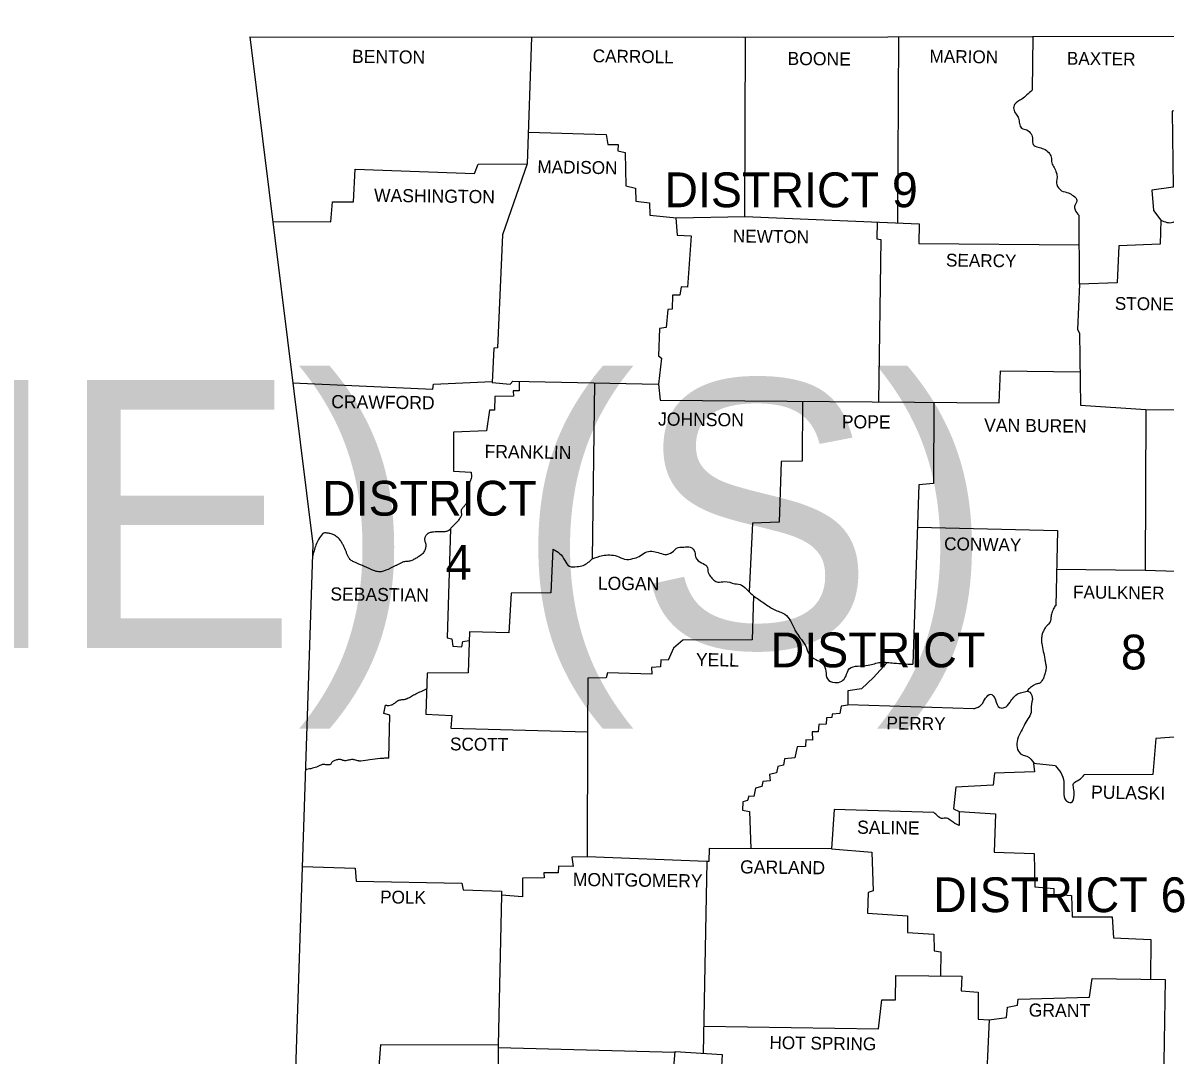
# Model space of a CAD drawing. Extents: x 164 to 3385, y 68 to 2119.
# Drawn here: x 2632.5 to 2994.5, y 1627.9 to 1955.2 of the extents above; entities that cross this region are included whole.
import ezdxf

# ---------------------------------------------------------------- set-up
doc = ezdxf.new("R2010")
doc.units = 0
doc.layers.add('2', color=7, linetype='Continuous')
doc.layers.add('Default', color=7, linetype='Continuous')

msp = doc.modelspace()

# ---------------------------------------------------------------- linework, layer by layer
at = {"layer": 'Default'}
msp.add_line((2849.29, 1689.32), (2848.17, 1628.55), dxfattribs=at)
for points in [[(2704.43, 1950.7), (2860.9, 1950.6), (2998.22, 1950.89), (3160.21, 1953.41), (3235.3, 1955.15)], [(2704.43, 1950.7), (2724.46, 1789.87), (2715.75, 1527.33)], [(2793.76, 1950.65), (2792.39, 1910.44)], [(2792.74, 1920.53), (2817.36, 1919.73), (2817.94, 1916.64), (2821.23, 1916.54), (2821.13, 1914.6), (2823.45, 1914.02), (2823.65, 1903.48), (2826.65, 1902.8), (2826.84, 1898.64), (2831.1, 1898.06), (2831.29, 1894.19), (2839.71, 1893.32), (2861.39, 1893.8), (2861.58, 1950.61)], [(2910.07, 1950.71), (2909.77, 1891.76)], [(2952.65, 1950.8), (2952.45, 1933.77)], [(2998.21, 1950.89), (2998.41, 1927.28), (2996.77, 1927.19), (2997.06, 1903.09), (2990.28, 1902.12), (2990.86, 1895.64), (2993.19, 1892.64), (2992.99, 1884.99), (2979.83, 1884.51), (2979.35, 1872.7), (2967.35, 1872.32), (2966.77, 1857.99), (2967.45, 1856.83), (2967.74, 1833.99), (2988.45, 1832.64), (2988.16, 1781.64), (3004.61, 1781.16), (3004.61, 1729.29), (2991.64, 1728.32), (2990.67, 1716.9), (2968.9, 1716.81)], [(2711.72, 1892.16), (2730.17, 1892.06), (2730.65, 1898.44), (2737.33, 1898.44), (2737.91, 1908.8), (2775.65, 1907.44), (2776.81, 1910.35), (2792.39, 1910.44), (2784.55, 1887.99), (2783, 1852.09), (2781.84, 1851.99), (2781.26, 1841.16), (2786.97, 1840.67), (2787.84, 1841.54), (2834, 1840.67), (2834.49, 1835.54)], [(2839.5, 1893.34), (2839.9, 1887.9), (2844.36, 1887.61), (2843.19, 1871.35), (2841.16, 1871.45), (2840.78, 1868.83), (2838.45, 1868.83), (2838.36, 1864.38), (2836.9, 1864.28), (2836.42, 1858.57), (2834.29, 1858.28), (2834, 1849.57), (2834.97, 1848.9), (2834, 1840.67)], [(2861.39, 1893.8), (2916.55, 1891.48), (2916.45, 1885.19), (2967.29, 1884.8)], [(2967.35, 1872.32), (2967.25, 1894.09)], [(2903.29, 1892.03), (2903.19, 1886.73), (2904.45, 1886.44), (2903.67, 1834.98)], [(2834.49, 1835.54), (2941.9, 1834.67), (2942.38, 1844.83), (2967.6, 1844.54)], [(2718.08, 1841.08), (2762.49, 1839.03), (2762.68, 1840.58), (2781.28, 1841.46)], [(2789.78, 1841.51), (2789.78, 1838.54), (2787.94, 1838.54), (2788.04, 1836.8), (2782.13, 1836.7), (2782.04, 1832.35), (2780.39, 1832.35), (2779.52, 1825.87), (2769.07, 1825.38), (2768.97, 1813.09), (2774.58, 1812.71)], [(2813.68, 1841.06), (2813, 1785.22)], [(2879.61, 1835.18), (2879.51, 1816.22), (2872.83, 1816.12), (2872.25, 1796.87), (2863.74, 1796.58), (2862.68, 1774.86)], [(2921.29, 1834.84), (2921.09, 1809.12), (2916.45, 1808.74), (2914.61, 1751.84)], [(2988.45, 1832.64), (3038.19, 1832.35), (3042.44, 1834.38), (3042.15, 1796.54), (3039.25, 1795.29), (3036.64, 1793.06), (3035.77, 1792.19), (3035.67, 1781.35), (2998.02, 1781.35)], [(2768.04, 1794.78), (2767.04, 1760.26), (2768.49, 1759.87), (2768.78, 1757.55), (2771.68, 1757.35), (2771.97, 1759), (2774.02, 1759.34)], [(2916.01, 1795.29), (2960.48, 1794.22), (2959.9, 1770.32)], [(2800.52, 1788.32), (2799.84, 1774.48), (2787.26, 1774.38), (2786.58, 1761.8), (2774.1, 1762.09), (2773.71, 1749.13), (2760.65, 1749.03), (2760.26, 1736.06), (2768.49, 1735.58), (2768.2, 1731.61), (2811.49, 1730.41)], [(2960, 1782.03), (2988.16, 1781.64)], [(2864.1, 1773.51), (2863.71, 1759.58), (2841.65, 1759.48), (2838.74, 1756.97), (2837.1, 1753.09), (2834.68, 1753.29), (2834.58, 1751.06), (2831.78, 1750.77), (2831.87, 1748.74), (2817.84, 1749.13), (2817.36, 1747.58), (2811.55, 1747.38), (2811.49, 1730.41)], [(2906.44, 1752.35), (2902.13, 1747.68), (2898.35, 1744.09), (2894, 1743.42), (2894, 1738.87), (2891.87, 1738.58), (2891.48, 1736.26), (2889.06, 1736.06), (2888.87, 1735), (2887.22, 1734.9), (2887.13, 1732.87), (2884.81, 1732.77), (2884.61, 1730.45), (2882.68, 1730.45), (2882.77, 1727.74), (2880.64, 1727.93), (2880.55, 1725.8), (2877.93, 1725.61), (2877.16, 1722.13), (2873.87, 1721.84), (2873.58, 1719.9), (2871.84, 1719.42), (2871.35, 1717.39), (2869.13, 1716.9), (2869.32, 1714.87), (2867.1, 1714.68), (2866.71, 1713.13), (2864.68, 1712.55), (2864.19, 1709.93), (2862.65, 1710.03), (2862.16, 1708.68), (2860.71, 1708.19), (2860.61, 1705.58), (2862.84, 1705.19), (2863.24, 1693.42)], [(2748.55, 1722.03), (2748.84, 1735.68), (2746.91, 1736.26), (2747.49, 1738.87)], [(2933.96, 1737.71), (2894, 1738.97)], [(2811.49, 1730.41), (2811.36, 1690.77), (2806.52, 1690.68), (2806.91, 1687.77), (2802.26, 1687.87), (2802.16, 1685.74), (2797.62, 1685.74), (2797.71, 1684.19), (2790.94, 1684), (2790.84, 1678.1), (2784.26, 1678.68), (2783.2, 1631.07), (2745.94, 1631.16), (2745.07, 1620.13), (2746.42, 1619.16), (2746.33, 1606.78), (2718.43, 1608)], [(2959.8, 1719.61), (2952.83, 1720.39), (2953.12, 1717.77), (2940.45, 1717.29), (2940.06, 1713.52), (2928.16, 1712.84), (2927.48, 1706.06), (2929.22, 1705.19), (2929.22, 1700.74)], [(2921.29, 1704.81), (2889.64, 1705.77), (2888.77, 1693.29), (2850.07, 1693.48), (2849.91, 1689.3)], [(2929.22, 1705.14), (2940.74, 1704.42), (2940.35, 1692.32), (2953.03, 1691.84), (2953.22, 1681.29), (2959.22, 1680.81), (2959.22, 1678.97), (2964.83, 1678.58), (2965.03, 1671.81), (2977.8, 1671.81), (2978.19, 1665.13), (2989.99, 1664.55), (2989.9, 1651.95)], [(2849.29, 1689.32), (2811.36, 1690.77)], [(2888.77, 1693.29), (2901.64, 1692.23), (2902.03, 1680.03), (2900.39, 1679.45), (2900.19, 1672.97), (2912.87, 1672.1), (2912.87, 1666.77), (2921.29, 1666.29), (2921.38, 1660.97), (2923.42, 1660.68), (2923.31, 1653.03)], [(2721.07, 1687.77), (2737.81, 1687.19), (2738.2, 1683.13), (2771.68, 1682.45), (2772.07, 1680.32), (2784.26, 1679.94), (2784.26, 1678.68)], [(2849.91, 1689.3), (2849.29, 1689.32)], [(2848.32, 1637.07), (2903.68, 1636.29), (2904.74, 1645.49), (2909.09, 1645.49), (2909.19, 1653.23), (2930.09, 1652.94), (2929.9, 1648.29), (2935.32, 1647.9), (2935.32, 1639.39), (2938.8, 1639.1), (2938.76, 1638.21)], [(2938.8, 1639.1), (2944.22, 1639.87), (2944.61, 1643.16), (2947.8, 1643.74), (2948, 1645.68), (2970.54, 1646.36), (2971.41, 1652.26), (2994.54, 1651.87)], [(2994.54, 1651.87), (2993.96, 1612.58), (2991.74, 1612.49), (2991.45, 1588.2)], [(2938.8, 1639.1), (2937.64, 1613.74), (2936.77, 1614.03), (2936.87, 1600.98)], [(2783.2, 1631.07), (2783.2, 1618.2), (2785.33, 1617.81), (2785.13, 1605.81), (2797.91, 1604.84), (2796.36, 1540.88), (2770.04, 1541.55)], [(2783.2, 1630.39), (2839.21, 1628.92)], [(2836.9, 1611.23), (2836.71, 1616.55), (2838.26, 1616.65), (2839.23, 1629.13), (2854.13, 1628.16), (2853.74, 1620.52), (2873, 1619.45), (2873.1, 1614.81), (2890.51, 1613.74), (2893.51, 1608.52), (2891.68, 1606.2), (2892.55, 1602.62), (2955.64, 1600.29)]]:
    msp.add_lwpolyline(points, dxfattribs=at)
for points in [[(2952.45, 1933.77), (2950.71, 1932.31), (2949.16, 1930.96), (2946.83, 1929.31), (2946.54, 1927.77), (2947.32, 1926.22), (2948.09, 1924.96), (2948.38, 1923.22), (2949.06, 1921.77), (2950.71, 1921.19), (2952.06, 1919.93), (2952.54, 1918.19), (2952.74, 1916.54), (2954.29, 1915.77), (2956.03, 1915.19), (2957.67, 1914.02), (2958.45, 1912.57), (2958.64, 1910.73), (2959.32, 1909.28), (2960.09, 1907.54), (2960.29, 1906.09), (2960.09, 1904.64), (2960.48, 1903.28), (2961.74, 1901.93), (2963.96, 1901.25), (2965.51, 1900.28), (2966.58, 1898.93), (2965.9, 1897.28), (2965.99, 1895.83), (2967.25, 1894.09)], [(2993.19, 1892.64), (2997.06, 1891.96), (2999.38, 1892.83), (3001.03, 1890.32), (3001.9, 1888.38), (3003.35, 1885.57), (3005.67, 1884.7), (3007.41, 1883.15), (3007.41, 1881.51), (3005.86, 1879.96), (3004.7, 1878.41), (3005.09, 1876.57), (3005.48, 1874.06), (3005.48, 1871.64), (3004.9, 1869.41), (3004.41, 1867.38), (3004.9, 1865.64), (3006.73, 1865.93), (3008.67, 1867.38), (3010.7, 1867.38), (3012.64, 1866.32), (3014.67, 1864.48), (3016.7, 1864.86), (3018.35, 1865.35), (3020.67, 1866.03), (3022.31, 1865.15), (3023.77, 1863.99), (3025.51, 1862.16), (3027.15, 1860.99), (3029.28, 1859.93), (3031.9, 1859.25), (3034.31, 1857.61), (3034.7, 1854.8), (3034.6, 1852.38), (3034.41, 1849.38), (3034.22, 1846.09), (3034.51, 1842.9), (3035.57, 1840.77), (3036.93, 1838.25), (3037.31, 1835.93), (3037.22, 1832.25)], [(2774.58, 1812.71), (2774.67, 1812.2), (2774.71, 1811.68), (2774.58, 1810.67), (2774.41, 1810.14), (2774.21, 1809.61), (2774, 1809.08), (2773.81, 1808.54), (2773.33, 1806.71), (2773.33, 1806.11), (2773.48, 1805.5), (2773.62, 1804.89), (2773.65, 1804.59), (2773.62, 1804.29), (2773.26, 1803.29), (2772.75, 1802.35), (2772.45, 1801.94), (2772.1, 1801.58), (2771.77, 1801.21), (2771.49, 1800.8), (2771.41, 1800.34), (2771.49, 1799.84), (2771.58, 1799.33), (2771.49, 1798.87), (2771.33, 1798.6), (2771.17, 1798.33), (2770.83, 1797.8), (2770.45, 1797.3), (2770.04, 1796.83), (2768.49, 1795.29), (2767.87, 1794.59), (2767.54, 1794.27), (2767.35, 1794.14), (2767.24, 1794.08), (2767.13, 1794.03), (2766.54, 1793.87), (2765.93, 1793.83), (2765.32, 1793.84), (2765.02, 1793.84), (2764.71, 1793.83), (2763.7, 1793.79), (2762.68, 1793.74), (2762.16, 1793.69), (2761.64, 1793.58), (2761.14, 1793.38), (2760.9, 1793.24), (2760.65, 1793.06), (2760.33, 1792.74), (2760.11, 1792.39), (2759.96, 1792.01), (2759.88, 1791.61), (2759.9, 1791.05), (2760.06, 1790.5), (2760.23, 1789.94), (2760.26, 1789.38), (2760.17, 1788.83), (2760.03, 1788.29), (2759.49, 1787.25), (2758.53, 1786.31), (2757.46, 1785.61), (2756.37, 1785.01), (2755.23, 1784.54), (2754.65, 1784.42), (2754.06, 1784.38), (2753.47, 1784.32), (2752.91, 1784.16), (2752.1, 1783.79), (2751.31, 1783.39), (2750.52, 1783), (2749.72, 1782.61), (2746.81, 1781.35), (2746.06, 1781.17), (2745.26, 1781.16), (2744.47, 1781.29), (2743.72, 1781.54), (2740.81, 1782.8), (2738.2, 1783.96), (2737.66, 1784.19), (2737.12, 1784.43), (2736.61, 1784.73), (2736.38, 1784.91), (2736.27, 1785.01), (2736.17, 1785.13), (2735.62, 1785.96), (2735.24, 1786.87), (2734.91, 1787.8), (2734.73, 1788.26), (2734.52, 1788.71), (2734.01, 1789.68), (2733.46, 1790.64), (2733.09, 1791.19), (2732.66, 1791.69), (2732.18, 1792.15), (2731.91, 1792.37), (2731.62, 1792.58), (2731.08, 1792.88), (2730.53, 1793.09), (2729.96, 1793.24), (2729.39, 1793.35), (2728.93, 1793.44), (2728.44, 1793.49), (2727.97, 1793.43), (2727.75, 1793.32), (2727.65, 1793.25), (2727.55, 1793.16), (2726.25, 1791.43), (2725.41, 1789.63), (2724.83, 1787.78), (2724.33, 1785.9)], [(2800.52, 1788.32), (2802.65, 1786.96), (2804.29, 1784.74), (2805.74, 1782.9), (2808.16, 1782.8), (2810.1, 1783.19), (2813, 1785.22)], [(2813, 1785.22), (2816.2, 1786.29), (2818.52, 1786.48), (2820.84, 1786.09), (2823.26, 1785.13), (2825.87, 1785.32), (2827.81, 1786), (2829.74, 1787.25), (2831.87, 1787.64), (2833.9, 1787.25), (2836.03, 1786.67), (2838.36, 1787.35), (2839.71, 1788.61), (2842.03, 1789), (2844.07, 1789), (2845.52, 1787.35), (2845.81, 1785.61), (2847.65, 1783.96), (2849.29, 1782.9), (2849.77, 1780.87), (2850.65, 1779.42), (2851.52, 1778.45), (2852.77, 1777.87), (2854.9, 1778.06), (2858.19, 1777.38), (2860.32, 1776.9), (2862.26, 1775.25), (2864.1, 1773.51)], [(2864.1, 1773.51), (2867.48, 1771.19), (2870.68, 1769.16), (2873.97, 1767.71), (2875.81, 1765.58), (2877.45, 1762.29), (2878.81, 1760.26), (2880.55, 1757.74), (2881.81, 1754.93), (2883.84, 1753.38), (2885.97, 1752.03), (2887.03, 1749.61), (2887.51, 1747.19), (2889.84, 1746.03), (2892.06, 1746.51), (2893.32, 1747.97), (2894.48, 1750.48), (2897.1, 1751.26), (2900.48, 1751.55), (2904.35, 1752.42), (2908.61, 1752.22), (2914.61, 1751.84)], [(2959.9, 1770.32), (2959.76, 1770.36), (2959.61, 1770.23), (2959.28, 1769.65), (2958.94, 1768.84), (2958.78, 1768.44), (2958.64, 1768.09), (2958.44, 1767.36), (2958.36, 1766.61), (2958.28, 1765.88), (2958.19, 1765.53), (2958.06, 1765.19), (2957.73, 1764.7), (2957.31, 1764.27), (2956.88, 1763.83), (2956.51, 1763.35), (2956.21, 1762.84), (2955.94, 1762.32), (2955.54, 1761.22), (2955.47, 1760.87), (2955.42, 1760.52), (2955.35, 1759.82), (2955.36, 1759.11), (2955.45, 1758.42), (2955.93, 1755.9), (2956.41, 1753.48), (2956.62, 1752.37), (2956.72, 1751.81), (2956.8, 1751.26), (2956.82, 1750.55), (2956.71, 1749.85), (2956.53, 1749.15), (2956.42, 1748.8), (2956.32, 1748.45), (2956.11, 1747.79), (2955.85, 1747.16), (2955.51, 1746.57), (2955.3, 1746.3), (2955.18, 1746.16), (2955.06, 1746.03), (2954.62, 1745.76), (2954.11, 1745.64), (2953.59, 1745.55), (2953.12, 1745.35), (2952.81, 1745.13), (2952.48, 1744.9), (2951.85, 1744.42), (2951.27, 1743.9), (2950.77, 1743.3)], [(2747.49, 1738.87), (2748.02, 1738.8), (2748.56, 1738.81), (2749.36, 1738.97), (2749.49, 1739.02), (2749.62, 1739.06), (2749.89, 1739.2), (2750.15, 1739.36), (2750.64, 1739.75), (2751.12, 1740.13), (2751.51, 1740.36), (2751.65, 1740.42), (2751.98, 1740.51), (2752.32, 1740.58), (2753.01, 1740.67), (2753.71, 1740.78), (2754.04, 1740.87), (2754.36, 1741), (2755.04, 1741.35), (2755.71, 1741.73), (2756.38, 1742.1), (2757.07, 1742.45), (2760.5, 1744.02)], [(2933.96, 1737.71), (2936.38, 1739.06), (2937.64, 1741.09), (2939.19, 1742.35), (2940.74, 1740.61), (2942.09, 1738.09), (2943.54, 1738.09), (2945.38, 1739.84), (2946.54, 1741.39), (2948, 1742.55), (2949.54, 1743.03), (2951.19, 1743.22), (2952.45, 1741.39), (2952.06, 1738.48), (2952.06, 1736.55), (2951, 1734.51), (2949.83, 1732.39), (2948.58, 1729.97), (2947.61, 1727.35), (2947.8, 1724.84), (2949.16, 1723.19), (2950.71, 1722.71), (2953.05, 1720.36)], [(2748.55, 1722.03), (2747.85, 1722.04), (2747.15, 1722.03), (2745.75, 1721.93), (2742.55, 1721.55), (2739.65, 1721.16), (2739.32, 1721.15), (2739, 1721.19), (2738.34, 1721.35), (2737.69, 1721.54), (2737.2, 1721.63), (2737.04, 1721.64), (2736.43, 1721.59), (2735.83, 1721.46), (2735.22, 1721.32), (2734.62, 1721.26), (2734.21, 1721.32), (2733.8, 1721.45), (2733.39, 1721.58), (2732.97, 1721.64), (2732.47, 1721.62), (2731.96, 1721.52), (2731.45, 1721.36), (2730.94, 1721.16), (2730.61, 1720.91), (2730.35, 1720.56), (2730.1, 1720.22), (2729.78, 1720), (2729.49, 1719.93), (2729.19, 1719.92), (2728.57, 1719.99), (2727.95, 1720.07), (2727.5, 1720.04), (2727.36, 1720), (2726.93, 1719.82), (2726.5, 1719.6), (2726.07, 1719.39), (2725.62, 1719.22), (2724.74, 1718.97), (2723.86, 1718.74), (2722.98, 1718.57), (2722.09, 1718.43)], [(2959.8, 1719.61), (2961.45, 1717.48), (2962.41, 1714.58), (2962.41, 1711.29), (2963.19, 1708.58), (2964.74, 1708), (2965.7, 1710.32), (2965.51, 1712.64), (2965.51, 1714), (2967.16, 1715.16), (2968.9, 1716.81)], [(2929.22, 1700.74), (2926.71, 1702.19), (2925.26, 1703.06), (2923.71, 1702.97), (2922.45, 1703.74), (2921.29, 1704.81)]]:
    msp.add_spline(points, degree=3, dxfattribs=at)

# ---------------------------------------------------------------- texts
at = {"layer": '2'}
msp.add_text('(EAST OF LAFAYETTE CO.  LINE) (S)', height=85, dxfattribs=at).set_placement((963.61, 1756.95))
at = {"layer": 'Default'}
for s, height, rotation, p in [('BENTON', 4.162, 359.2527, (2736.84, 1942.47)), ('CARROLL', 4.065, 359.1481, (2813.1, 1942.67)), ('BOONE', 4.162, 359.4001, (2874.84, 1941.8)), ('MARION', 4.065, 359.1854, (2919.84, 1942.57)), ('BAXTER', 4.065, 359.2559, (2963.38, 1941.89)), ('MADISON', 4.065, 359.0906, (2795.58, 1907.54)), ('WASHINGTON', 4.161, 359.232, (2743.81, 1898.44)), ('NEWTON', 4.065, 359.2717, (2857.52, 1885.57)), ('SEARCY', 4.064, 359.2527, (2925.06, 1877.93)), ('STONE', 4.064, 359.4001, (2978.58, 1864.19)), ('CRAWFORD', 4.161, 359.2771, (2730.26, 1833.03)), ('JOHNSON', 4.162, 359.3514, (2833.81, 1827.51)), ('POPE', 4.162, 359.6155, (2892.06, 1826.64)), ('VAN BUREN', 4.162, 359.3508, (2937.16, 1825.58)), ('FRANKLIN', 4.162, 359.1815, (2778.84, 1817.25)), ('CONWAY', 4.064, 359.0371, (2924.48, 1788.03)), ('LOGAN', 4.162, 359.3969, (2814.74, 1775.45)), ('SEBASTIAN', 4.161, 359.2816, (2729.97, 1772.06)), ('FAULKNER', 4.065, 359.2486, (2965.32, 1772.74)), ('YELL', 4.162, 359.1987, (2845.81, 1751.26)), ('PERRY', 4.065, 359.0858, (2906.19, 1731.22)), ('SCOTT', 4.065, 359.4063, (2767.91, 1724.55)), ('PULASKI', 4.162, 359.053, (2971.03, 1709.26)), ('SALINE', 4.162, 359.1491, (2896.9, 1698.13)), ('GARLAND', 4.162, 359.3657, (2859.84, 1685.55)), ('MONTGOMERY', 4.162, 359.2944, (2806.81, 1681.58)), ('POLK', 4.064, 359.2152, (2745.75, 1676.06)), ('GRANT', 4.162, 359.4032, (2951.29, 1640.16)), ('HOT SPRING', 4.065, 359.2216, (2869.13, 1629.9))]:
    msp.add_text(s, height=height, rotation=rotation, dxfattribs=at).set_placement(p)
for s, height, p in [('DISTRICT 9', 11.032, (2835.84, 1896.7)), ('DISTRICT', 11.032, (2727.37, 1798.94)), ('4', 11.03, (2766.57, 1778.62)), ('DISTRICT', 11.032, (2869.52, 1750.87)), ('8', 11.03, (2980.51, 1750.19)), ('DISTRICT 6', 11.032, (2921, 1673.26))]:
    msp.add_text(s, height=height, dxfattribs=at).set_placement(p)

doc.saveas('drawing.dxf')
